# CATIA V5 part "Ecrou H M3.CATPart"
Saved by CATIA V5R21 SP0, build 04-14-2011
Part number: Ecrou H M3
Material "Acier": density 7860 kg/m3, Young's modulus 2e+11 Pa, Poisson ratio 0.266, thermal expansion 1.17e-05 1/K
Bounding box of the stored display mesh (mm): x -2.5 to 2.5, y -2.887 to 2.887, z 0 to 2
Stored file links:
  C:\Users\Utilisateur\Desktop\Fichiers à télécharger dans l'ouvrage\Exercice 9 Pompe de ventilation.CATDrawing (corrigé)\Ecrou H M3.CATPart
  C:\Program Files\Dassault Systemes\B21\win_b64\startup\materials\French\Catalog.CATMaterial
  C:\Users\Utilisateur\Desktop\Fichiers à télécharger dans l'ouvrage\Exercice 9 Pompe de ventilation.CATDrawing (corrigé)\CATIA_EnvironmentMap_Satin_512x512.jpg
  C:\Users\Olivier\Desktop\redaction CATIA (local)\pompe à moteur de ventilation refait\Pompe_a_moteur_de_ventilation.CATProduct
  C:\Users\Olivier\Desktop\redaction CATIA (local)\pompe à moteur de ventilation refait\Ecrou a collerette M5.CATPart
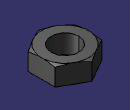
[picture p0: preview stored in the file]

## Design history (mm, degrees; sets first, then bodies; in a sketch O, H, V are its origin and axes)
Body1 (main body), material "Acier"
  Sketch1 on xy-plane, origin (0, 0, 0), H (1, 0, 0), V (0, 1, 0)
    circle A1 centre (0, 0) radius 1.5
    point P1 (2.5, -1.4434)
    point P2 (2.5, 1.4434)
    point P3 (0, 2.8868)
    point P4 (-2.5, 1.4434)
    point P5 (-2.5, -1.4434)
    point P6 (0, -2.8868)
    point P7 (2.5, 0)
    line L1 (2.5, -1.4434) -> (2.5, 1.4434)
    line L2 (2.5, 1.4434) -> (0, 2.8868)
    line L3 (0, 2.8868) -> (-2.5, 1.4434)
    line L4 (-2.5, 1.4434) -> (-2.5, -1.4434)
    line L5 (-2.5, -1.4434) -> (0, -2.8868)
    line L6 (0, -2.8868) -> (2.5, -1.4434)
    construction line L7 (0, 0) -> (2.5, 0)
    construction circle A2 centre (0, 0) radius 2.8868
    construction arc A3 centre (-2.5, -1.4434) radius 2.8868 from (-2.5, 1.4434) to (0, -2.8868) cw
    construction arc A4 centre (2.5, 1.4434) radius 2.8868 from (0, 2.8868) to (2.5, -1.4434) ccw
    distance L1 L4 = 5
    horizontal: L7 H
    coincidence: A2 P1, A2 P2, A2 P3, A2 P4, A2 P5, A2 P6, A3 O, A4 O
    midpoint: P7 L1
  Pad1: profile Sketch1, direction (0, 0, 1), length 2
  Sketch2 on yz-plane, origin (0, 0, 0), H (0, 1, 0), V (0, 0, 1)
    line L1 (2.4595, 2.0276) -> (2.9071, 2.0276)
    point P1 (2.4595, 2.0276)
    line L2 (2.9071, 2.0276) -> (2.9071, 1.8177)
    line L3 (2.9071, 1.8177) -> (2.4663, 2.0244)
    horizontal: L1 H
    vertical: L2 V
    coincidence: L3 P1
  Groove1: profile Sketch2, axis Sketch2.V, angle 360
